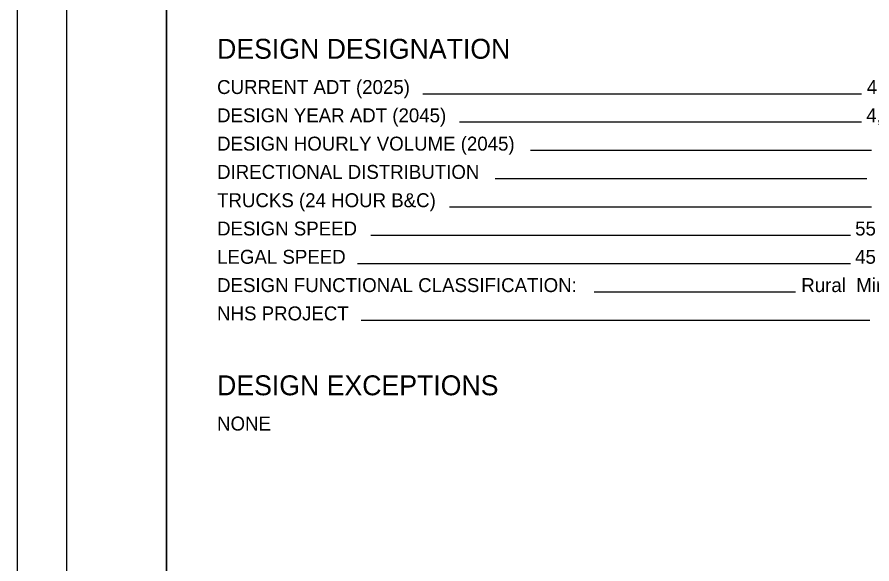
# Model space of a CAD drawing. Extents: x -84548 to 2262448, y -162180 to 525962.
# Drawn here: x 0 to 45287, y 29102 to 58091 of the extents above; entities that cross this region are included whole.
import ezdxf

# ---------------------------------------------------------------- set-up
doc = ezdxf.new("R2010")
doc.units = 0
for name, color, linetype in [('GM_X_Adjacent_County', 7, 'Continuous'), ('GM_X_County', 7, 'Continuous'), ('GM_X_Township', 7, 'Continuous')]:
    doc.layers.add(name, color=color, linetype=linetype)

msp = doc.modelspace()

# ---------------------------------------------------------------- linework, layer by layer
at = {"layer": 'GM_X_Adjacent_County'}
for points in [[(2640, 113520), (7920, 113520), (7920, 2640), (2640, 2640)], [(7920, 113520), (176880, 113520), (176880, 2640), (7920, 2640)]]:
    msp.add_lwpolyline(points, close=True, dxfattribs=at)
at = {"layer": 'GM_X_County'}
for p, q in [((44743, 54013), (21491, 54013)), ((44743, 52513), (23445, 52513)), ((45262, 51013), (27202, 51013)), ((45023, 49513), (25320, 49513)), ((45262, 48013), (22910, 48013)), ((44152, 46513), (18735, 46513)), ((44152, 45013), (18034, 45013)), ((41246, 43513), (30578, 43513)), ((45177, 42013), (18234, 42013))]:
    msp.add_line(p, q, dxfattribs=at)
at = {"layer": 'GM_X_Township'}
msp.add_lwpolyline([(0, 0), (179520, 0), (179520, 116160), (0, 116160)], close=True, dxfattribs=at)

# ---------------------------------------------------------------- texts
at = {"layer": 'GM_X_County'}
for s, height, p in [('DESIGN DESIGNATION', 1056, (10595, 55882)), ('CURRENT ADT (2025)', 739.2, (10595, 54013)), ('4,400', 739.2, (45015, 54013)), ('DESIGN YEAR ADT (2045)', 739.2, (10595, 52513)), ('4,400', 739.2, (44985, 52513)), ('DESIGN HOURLY VOLUME (2045)', 739.2, (10595, 51013)), ('DIRECTIONAL DISTRIBUTION', 739.2, (10595, 49513)), ('TRUCKS (24 HOUR B&C)', 739.2, (10595, 48013)), ('DESIGN SPEED', 739.2, (10595, 46513)), ('55 MPH', 739.2, (44399, 46513)), ('LEGAL SPEED', 739.2, (10595, 45013)), ('45 MPH', 739.2, (44399, 45013)), ('DESIGN FUNCTIONAL CLASSIFICATION:', 739.2, (10595, 43513)), ('Rural  Minor  Arterial', 739.2, (41546, 43513)), ('NHS PROJECT', 739.2, (10595, 42013)), ('DESIGN EXCEPTIONS', 1056, (10595, 38042)), ('NONE', 739.2, (10595, 36173))]:
    msp.add_text(s, height=height, dxfattribs=at).set_placement(p)

doc.saveas('drawing.dxf')
